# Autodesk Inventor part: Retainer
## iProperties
Shininess: 77.0
Length Units: 11269
Angle Units: 11279
Time Units: 11290
Mass Units: 11283
Length Display Precision: 3
Angle Display Precision: 2
Created: 2002-01
Part Number: Retainer
Document SubType Name: Modeling
Designer: ***
Density: 0.0
Volumn: 0.0
Area: 0.0
PropertySet Name: Model Information
Control State: 0
Master: False
Checked Out: False
Author: ***
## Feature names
1. Extrusion2
2. Hole1
3. Circular Pattern1
